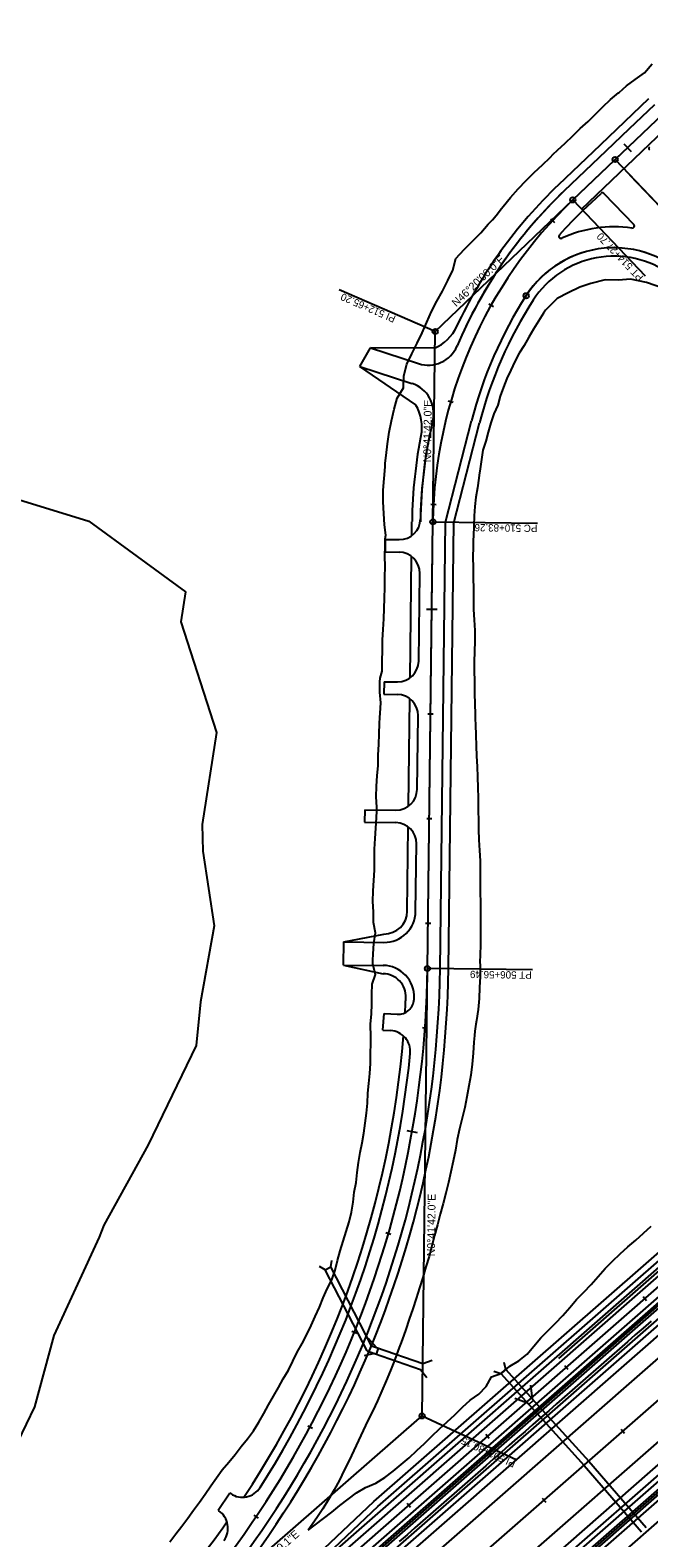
# Model space of a CAD drawing. Extents: x 1300404 to 1323571, y 234004 to 252077.
# Drawn here: x 1309592 to 1310184, y 240349 to 241789 of the extents above; entities that cross this region are included whole.
import ezdxf

# ---------------------------------------------------------------- set-up
doc = ezdxf.new("R2010")
doc.units = 0
for name, color, linetype in [('R_Barrier Wall', 7, 'Continuous'), ('R_Box Culvert', 7, 'Continuous'), ('R_Const Limits', 7, 'Continuous'), ('R_Draft', 7, 'Continuous'), ('R_Exist Box Culvert', 7, 'Continuous'), ('R_Future', 7, 'Continuous'), ('R_Horz Alg Annot', 7, 'Continuous'), ('R_Horz Alg Annot Leader', 7, 'Continuous'), ('R_Horz Alg Major Ticks', 7, 'Continuous'), ('R_Horz Alg Minor Ticks', 7, 'Continuous'), ('R_Horz Alg Tangents', 7, 'Continuous'), ('R_Horz Alg Tangents Text', 7, 'Continuous'), ('R_Lane Edge', 7, 'Continuous'), ('R_Proposed', 7, 'Continuous'), ('R_Shoulder', 7, 'Continuous'), ('T_Drafting', 7, 'Continuous')]:
    doc.layers.add(name, color=color, linetype=linetype)

msp = doc.modelspace()

# ---------------------------------------------------------------- linework, layer by layer
at = {"layer": 'R_Barrier Wall'}
for p, q in [((1309593.6, 240046.8), (1310899.2, 241188.4)), ((1309594.9, 240045.3), (1310900.5, 241186.9))]:
    msp.add_line(p, q, dxfattribs=at)
at = {"layer": 'R_Box Culvert'}
for p, q in [((1309874.4, 240605), (1309869, 240608.2)), ((1309874.4, 240605), (1309879.8, 240607.8)), ((1309914.5, 240527.6), (1309874.4, 240605)), ((1309879.8, 240607.8), (1309880.7, 240614)), ((1309918.7, 240532.5), (1309879.8, 240607.8)), ((1309918.7, 240532.5), (1309923.6, 240530.8)), ((1309923.5, 240524.5), (1309925.5, 240530.2)), ((1309923.6, 240530.8), (1309925.5, 240530.2)), ((1309914.5, 240527.6), (1309921.6, 240525.2)), ((1309921.6, 240525.2), (1309923.5, 240524.5)), ((1310045.5, 240516.9), (1310046.9, 240510.1)), ((1310035.9, 240508.2), (1310042.5, 240506)), ((1310042.5, 240506), (1310046.9, 240510.1)), ((1310042.5, 240506), (1310069.4, 240476.4)), ((1310046.9, 240510.1), (1310073.8, 240480.5)), ((1310069.4, 240476.4), (1310073.8, 240480.5))]:
    msp.add_line(p, q, dxfattribs=at)
at = {"layer": 'R_Const Limits'}
for points in [[(1309726, 240345.2), (1309731.7, 240352.8), (1309737.4, 240360.3), (1309743.1, 240367.8), (1309748.7, 240375.4), (1309754.3, 240383.1), (1309759.7, 240390.8), (1309765.1, 240398.6), (1309770.4, 240406.4), (1309776, 240414), (1309782.2, 240421.3), (1309788.4, 240428.6), (1309794.2, 240436.2), (1309800.2, 240443.7), (1309805.8, 240451.4), (1309810.9, 240459.5), (1309815.7, 240467.7), (1309820.4, 240476), (1309825, 240484.3), (1309829.7, 240492.7), (1309834.4, 240501), (1309839.4, 240509.2), (1309843.4, 240517.8), (1309847.7, 240526.4), (1309852.4, 240534.7), (1309857, 240543.2), (1309861.1, 240551.8), (1309865, 240560.6), (1309868.9, 240569.3), (1309872.5, 240578.2), (1309876.3, 240587), (1309881, 240595.5), (1309883.9, 240604.7), (1309886.2, 240614), (1309888.9, 240623.2), (1309891.7, 240632.4), (1309894.6, 240641.6), (1309897.3, 240650.8), (1309899.5, 240660.1), (1309901.2, 240669.6), (1309902.3, 240679.2), (1309904, 240688.6), (1309905.1, 240698.2), (1309906.4, 240707.6), (1309907.9, 240717.1), (1309909.9, 240726.4), (1309911.5, 240735.8), (1309912.8, 240745.2), (1309914, 240754.7), (1309914.8, 240764.2), (1309915.4, 240773.7), (1309916.3, 240783.2), (1309917.3, 240792.6), (1309917.8, 240802.1), (1309917.9, 240811.6), (1309918, 240821.2), (1309918.1, 240830.7), (1309917.9, 240836.3), (1309917.9, 240840.1), (1309918.5, 240846.3), (1309918.5, 240846.3), (1309918.8, 240849.6), (1309919.1, 240859), (1309919.1, 240868.5), (1309919.3, 240877.9), (1309922.7, 240887.3), (1309919.9, 240897), (1309920, 240900.6), (1309920.3, 240907), (1309920.9, 240917), (1309922.6, 240927), (1309920.6, 240937), (1309920.6, 240947), (1309920.1, 240957), (1309920.4, 240967), (1309921.1, 240977), (1309921.5, 240987), (1309921.7, 240997), (1309921.8, 241007), (1309922.4, 241017), (1309922.9, 241027), (1309923.5, 241037), (1309923.8, 241043.5), (1309923.8, 241047), (1309923.4, 241057), (1309923.5, 241067), (1309924.2, 241077), (1309925.1, 241087), (1309925.1, 241097), (1309925.9, 241107), (1309926.2, 241117), (1309926.5, 241126.9), (1309926.8, 241132.7), (1309927.2, 241136.9), (1309927.7, 241146.9), (1309926.9, 241156.9), (1309926.8, 241166.9), (1309927.2, 241170.2), (1309928.9, 241176.9), (1309929.1, 241186.9), (1309929.4, 241196.9), (1309929.4, 241206.9), (1309930, 241216.9), (1309930.5, 241226.9), (1309930.9, 241236.9), (1309931.2, 241246.9), (1309931.4, 241256.9), (1309931.6, 241266.9), (1309931.9, 241276.9), (1309931.4, 241286.9), (1309931.9, 241296.9), (1309931.9, 241303.5), (1309932.6, 241306.9), (1309931.2, 241316.9), (1309930.6, 241327.6), (1309930.1, 241338.8), (1309930.1, 241349.9), (1309930.8, 241361), (1309931.7, 241372.1), (1309932, 241375.7), (1309932.7, 241383.2), (1309934.1, 241394.3), (1309935.8, 241405.3), (1309937.9, 241416.3), (1309940.5, 241427.2), (1309943.4, 241437.9), (1309949.5, 241447.8), (1309949.8, 241459.3), (1309952.6, 241470.2), (1309957.3, 241480.3), (1309962.3, 241490.3), (1309967.3, 241500.3), (1309971.8, 241510.5), (1309976.2, 241520.7), (1309981.3, 241530.5), (1309986.7, 241540.2), (1309991.8, 241550.1), (1309996.6, 241560.2), (1309999.5, 241571.4), (1310007.3, 241579.7), (1310015.3, 241587.7), (1310023.2, 241595.7), (1310030.4, 241603.9), (1310030.5, 241604), (1310034.4, 241608.3), (1310037.9, 241612.3), (1310043.2, 241618.9), (1310044.7, 241620.9), (1310051.6, 241629.6), (1310058.9, 241637.8), (1310066.6, 241645.8), (1310074.5, 241653.4), (1310082.4, 241660.8), (1310089.5, 241667.8), (1310092.6, 241670.9), (1310096.7, 241674.8), (1310104, 241681.6), (1310111.3, 241688.4), (1310118.5, 241695.4), (1310126, 241702), (1310133, 241709.1), (1310140.1, 241716.2), (1310147.4, 241723), (1310155, 241729.6), (1310155.5, 241730), (1310162.5, 241736.2), (1310170.8, 241742.4), (1310179.9, 241748.7), (1310187.1, 241757.1)], [(1310166.5, 241551.6), (1310154.9, 241550.5), (1310142.4, 241550.8), (1310128.7, 241547.4), (1310118, 241543.8), (1310107, 241538.5), (1310096.2, 241532.9), (1310085.2, 241521.8), (1310083.3, 241518.9), (1310078.4, 241511.5), (1310073.7, 241503.9), (1310069.2, 241496.2), (1310064.9, 241488.3), (1310060.1, 241480.7), (1310055.8, 241472.9), (1310052, 241464.7), (1310048.1, 241456.6), (1310044.9, 241448.2), (1310041.7, 241439.8), (1310039.5, 241431.1), (1310035.8, 241422.8), (1310033, 241414.2), (1310030.5, 241405.5), (1310028, 241396.8), (1310025.2, 241388.2), (1310024.1, 241379.2), (1310022.7, 241370.3), (1310021.8, 241364.2), (1310021.4, 241361.3), (1310020, 241352.3), (1310018.6, 241343.4), (1310017.7, 241334.3), (1310017, 241325.3), (1310016.6, 241315.9), (1310016.2, 241305.9), (1310016.1, 241302.5), (1310015.9, 241295.9), (1310015.8, 241285.9), (1310015.9, 241275.9), (1310016.1, 241265.9), (1310016.4, 241255.9), (1310016.4, 241245.9), (1310016.4, 241235.9), (1310016.9, 241225.9), (1310017.6, 241215.9), (1310017.6, 241205.8), (1310017.3, 241195.9), (1310017.1, 241185.9), (1310017.1, 241175.9), (1310017.2, 241169.1), (1310017.3, 241165.9), (1310017.4, 241155.8), (1310017.6, 241145.8), (1310017.9, 241135.8), (1310017.9, 241131.6), (1310018.1, 241125.8), (1310018.6, 241115.8), (1310019, 241105.8), (1310019.3, 241095.8), (1310019.8, 241085.8), (1310020.2, 241075.8), (1310020.5, 241065.8), (1310020.7, 241055.8), (1310020.8, 241045.8), (1310020.9, 241042.3), (1310021, 241035.8), (1310021.1, 241025.8), (1310021.5, 241015.8), (1310022.2, 241005.8), (1310022.7, 240995.8), (1310022.6, 240985.8), (1310022.7, 240975.8), (1310022.8, 240965.8), (1310022.9, 240955.8), (1310022.9, 240945.8), (1310022.9, 240935.8), (1310022.9, 240925.8), (1310023, 240915.8), (1310022.6, 240905.8), (1310022.5, 240899.4), (1310022.6, 240895.8), (1310022.6, 240885.4), (1310022.2, 240874.9), (1310021.6, 240864.4), (1310020.7, 240853.9), (1310019.3, 240843.4), (1310018.7, 240839.8), (1310018.7, 240839.8), (1310017.7, 240833), (1310017.3, 240828.8), (1310016.7, 240822.6), (1310016.1, 240812.1), (1310015.1, 240801.6), (1310013.7, 240791.2), (1310012, 240780.9), (1310010, 240770.5), (1310007.9, 240760.2), (1310005.5, 240750), (1310002.8, 240739.8), (1310000.8, 240729.6), (1309999.1, 240719.3), (1309996.9, 240709), (1309994.8, 240698.8), (1309992.4, 240688.6), (1309989.9, 240678.4), (1309987.2, 240668.3), (1309984.6, 240658.2), (1309981.8, 240648.2), (1309979.1, 240638), (1309976.5, 240627.9), (1309973.8, 240617.8), (1309970.9, 240607.8), (1309967.9, 240597.7), (1309964.8, 240587.8), (1309961.6, 240577.8), (1309958.3, 240567.9), (1309954.8, 240558), (1309951.5, 240548.1), (1309948, 240538.2), (1309944.4, 240528.4), (1309940.7, 240518.6), (1309936.8, 240508.8), (1309932.8, 240499.1), (1309928.6, 240489.5), (1309924.4, 240479.9), (1309919.9, 240470.4), (1309915.4, 240461), (1309910.9, 240451.5), (1309906.5, 240442), (1309902, 240432.5), (1309897.4, 240423), (1309892.8, 240413.6), (1309888.1, 240404.2), (1309883.1, 240394.9), (1309877.8, 240385.8), (1309872.2, 240376.9), (1309866.5, 240368), (1309860.5, 240359.4), (1309858.3, 240356.4)], [(1310197.3, 241542.9), (1310181.8, 241548.3), (1310166.5, 241551.6)], [(1309568.6, 241344.9), (1309648.3, 241320.2), (1309740.8, 241252.9), (1309738.6, 241238.5), (1309736.3, 241224.2), (1309770.5, 241118.4), (1309756.9, 241030.5), (1309757.2, 241017.8), (1309757.5, 241005.1), (1309768.3, 240933.7), (1309755.1, 240861.2), (1309751.1, 240819.5), (1309705.1, 240724.5), (1309662.8, 240647.6), (1309658.4, 240636.3), (1309615.1, 240542.2), (1309596.6, 240474.1), (1309564.7, 240408)], [(1309858.3, 240356.4), (1309864.9, 240361.4), (1309872.8, 240367.5), (1309880.7, 240373.7), (1309888.6, 240379.8), (1309896.5, 240386), (1309904.4, 240392.1), (1309913.2, 240397.2), (1309922.8, 240401.4), (1309931.5, 240406.6), (1309939.6, 240412.6), (1309947.3, 240419), (1309954.9, 240425.5), (1309962.2, 240432.4), (1309969.4, 240439.3), (1309976.6, 240446.3), (1309983.9, 240453.2), (1309991.2, 240459.9), (1309998.6, 240466.7), (1310005.7, 240473.8), (1310013, 240480.6), (1310021.3, 240486.4), (1310028.3, 240493.5), (1310033.5, 240502.7), (1310043.5, 240506.4), (1310051.2, 240512.9), (1310059.8, 240518.2), (1310067.5, 240524.6), (1310074, 240532.3), (1310080.6, 240540), (1310087.7, 240547.1), (1310094.8, 240554.2), (1310101.8, 240561.3), (1310108.4, 240569), (1310114.9, 240576.7), (1310121.9, 240583.9), (1310128.8, 240591.2), (1310135.5, 240598.7), (1310142.3, 240606.2), (1310149.3, 240613.4), (1310156.5, 240620.3), (1310164, 240626.9), (1310171.6, 240633.4), (1310179, 240640.1), (1310186.4, 240646.9)], [(1310186.1, 240556.1), (1310178.6, 240549.5), (1310171.1, 240542.9), (1310163.5, 240536.3), (1310156, 240529.7), (1310148.5, 240523.2), (1310141, 240516.6), (1310133.4, 240510), (1310125.9, 240503.4), (1310118.4, 240496.8), (1310110.8, 240490.2), (1310103.3, 240483.7), (1310095.8, 240477.1), (1310088.3, 240470.5), (1310080.7, 240463.9), (1310073.2, 240457.3), (1310065.7, 240450.7), (1310058.1, 240444.2), (1310050.6, 240437.6), (1310043.1, 240431), (1310035.6, 240424.4), (1310028, 240417.8), (1310020.5, 240411.2), (1310013, 240404.7), (1310005.4, 240398.1), (1309997.9, 240391.5), (1309990.4, 240384.9), (1309982.9, 240378.3), (1309975.3, 240371.8), (1309967.8, 240365.2), (1309960.3, 240358.6), (1309952.8, 240352), (1309945.2, 240345.4)]]:
    msp.add_lwpolyline(points, dxfattribs=at)
at = {"layer": 'R_Draft'}
for p, q in [((1308397, 238971.9), (1312368.4, 242444.5)), ((1308407.8, 238959.5), (1312379.2, 242432.1)), ((1308447.3, 238914.3), (1312418.7, 242386.9)), ((1308458.2, 238901.9), (1312429.6, 242374.5)), ((1309037.8, 239548.2), (1312137.6, 242258.7)), ((1309184.5, 239689.1), (1312131.4, 242265.9)), ((1309193.7, 239678.5), (1312140.6, 242255.3)), ((1309413.9, 239721.6), (1312065.7, 242040.4)), ((1309410.9, 239725), (1311988, 241978.4)), ((1309410.9, 239725), (1311988, 241978.4)), ((1310119.6, 241618.5), (1310206.2, 241701.1)), ((1309989.5, 241319.5), (1310014.4, 241416.3))]:
    msp.add_line(p, q, dxfattribs=at)
for centre, radius, start, end in [((1310150.7, 241481.5), 100, 43.6667, 147.1004), ((1310409.9, 241314.4), 408.4, 147.1626, 165.5481)]:
    msp.add_arc(centre, radius, start, end, dxfattribs=at)
at = {"layer": 'R_Exist Box Culvert'}
for p, q in [((1309923.6, 240530.8), (1309915.8, 240539.4)), ((1309923.6, 240530.8), (1309967.8, 240515.6)), ((1309921.6, 240525.2), (1309911.7, 240523)), ((1309921.6, 240525.2), (1309965.8, 240510)), ((1309967.8, 240515.6), (1309976.8, 240518.7)), ((1309965.8, 240510), (1309971.6, 240502.3)), ((1310070.8, 240494.8), (1310072.5, 240481.9)), ((1310055.9, 240482.4), (1310068, 240477.9)), ((1310068, 240477.9), (1310122.2, 240418.3)), ((1310072.5, 240481.9), (1310126.6, 240422.4)), ((1310122.2, 240418.3), (1310176.9, 240354.8)), ((1310126.6, 240422.4), (1310181.4, 240358.8))]:
    msp.add_line(p, q, dxfattribs=at)
at = {"layer": 'R_Future'}
for p, q in [((1311714.8, 241726.2), (1309950.4, 240183.5)), ((1311716.1, 241724.7), (1309951.7, 240182)), ((1311717.4, 241723.2), (1309953.1, 240180.5)), ((1311720, 241720.2), (1309955.7, 240177.5)), ((1310616.7, 240735.5), (1309965.6, 240166.2)), ((1309921, 240383.6), (1310222.1, 240646.9)), ((1309924.9, 240379), (1310226, 240642.3)), ((1310097.8, 240520.3), (1310231, 240636.7)), ((1309920.8, 240383.4), (1309702.3, 240177.7)), ((1309924.9, 240379), (1309706.3, 240173.3))]:
    msp.add_line(p, q, dxfattribs=at)
at = {"layer": 'R_Horz Alg Annot Leader'}
for points in [[(1310111.3, 241627.2), (1310180.4, 241554.8)], [(1309979.7, 241501.5), (1309888, 241541.4)], [(1309977.5, 241319.6), (1310077.5, 241318.4)], [(1310072.7, 240891.6), (1309972.3, 240892.9)], [(1309967.2, 240465.5), (1310057.9, 240423.5)]]:
    msp.add_lwpolyline(points, dxfattribs=at)
at = {"layer": 'R_Horz Alg Major Ticks'}
for points in [[(1310155.4, 241669.2), (1310148.2, 241662.3)], [(1310160.2, 241680.7), (1310167.1, 241673.5)], [(1309971.5, 241236.4), (1309981.5, 241236.3)], [(1309952.7, 240738.1), (1309962.6, 240736.4)]]:
    msp.add_lwpolyline(points, dxfattribs=at)
at = {"layer": 'R_Horz Alg Minor Ticks'}
for points in [[(1310090.1, 241609.1), (1310093.8, 241605.7)], [(1310031, 241527.9), (1310035.4, 241525.5)], [(1309992.2, 241435.4), (1309997, 241434)], [(1309975.5, 241336.5), (1309980.5, 241336.2)], [(1309972.8, 241136.4), (1309977.8, 241136.3)], [(1309971.6, 241036.4), (1309976.6, 241036.3)], [(1309970.4, 240936.4), (1309975.4, 240936.3)], [(1309967.5, 240836.6), (1309972.5, 240836.3)], [(1309932.6, 240640.6), (1309937.4, 240639.2)], [(1310178.6, 240579.6), (1310181.9, 240575.9)], [(1309900, 240546.4), (1309904.7, 240544.5)], [(1310103.4, 240513.8), (1310106.7, 240510.1)], [(1309857.8, 240456.1), (1309862.2, 240453.7)], [(1310028.1, 240448), (1310031.4, 240444.2)], [(1310157.4, 240452.8), (1310160.7, 240449)], [(1310082.1, 240386.9), (1310085.4, 240383.2)], [(1309806.3, 240370.7), (1309810.4, 240367.9)], [(1309952.8, 240382.2), (1309956.1, 240378.4)]]:
    msp.add_lwpolyline(points, dxfattribs=at)
at = {"layer": 'R_Horz Alg Tangents'}
for p, q in [((1309979.7, 241501.5), (1310111.3, 241627.2)), ((1309977.5, 241319.6), (1309979.7, 241501.5)), ((1309967.2, 240465.5), (1309972.3, 240892.9)), ((1309645, 240184.6), (1309967.2, 240465.5))]:
    msp.add_line(p, q, dxfattribs=at)
at = {"layer": 'R_Lane Edge'}
for p, q in [((1310165.2, 241695.2), (1310189.6, 241718.4)), ((1310143.5, 241674.4), (1310165.2, 241695.2)), ((1310103.1, 241635.8), (1310143.5, 241674.4)), ((1310121, 241617), (1310138.3, 241633.5)), ((1310141.1, 241633.5), (1310169.6, 241603.6)), ((1309907.7, 241468.2), (1309917.8, 241486)), ((1309917.8, 241486), (1309963.7, 241470.9)), ((1309907.7, 241468.2), (1309957.5, 241451.9)), ((1309989.5, 241319.5), (1310014.4, 241416.3)), ((1309984.3, 240892.7), (1309989.5, 241319.5)), ((1309932, 241302.9), (1309931.9, 241290.9)), ((1309932, 241302.9), (1309945.3, 241302.7)), ((1309931.9, 241290.9), (1309945.2, 241290.7)), ((1309963.9, 241186.5), (1309964.9, 241270.5)), ((1309579.8, 240062.7), (1310885.3, 241204.2)), ((1309589.7, 240051.4), (1310895.2, 241193)), ((1309930.9, 241166.9), (1309930.7, 241154.9)), ((1309930.9, 241166.9), (1309943.7, 241166.8)), ((1309930.7, 241154.9), (1309943.5, 241154.8)), ((1309962.4, 241064), (1309963.3, 241134.5)), ((1309912.3, 241044.6), (1309912.2, 241032.6)), ((1309912.3, 241044.6), (1309942.2, 241044.3)), ((1309912.2, 241032.6), (1309942, 241032.3)), ((1309961, 240947.5), (1309961.8, 241012)), ((1309892.1, 240896.3), (1309892.4, 240918.3)), ((1309892.4, 240918.3), (1309930.6, 240917.9)), ((1309892.1, 240896.3), (1309930, 240895.9)), ((1309929.7, 240834.2), (1309930.8, 240850.1)), ((1309930.8, 240850.1), (1309943.5, 240849.3)), ((1309929.7, 240834.2), (1309937.3, 240833.7)), ((1309772, 240375.4), (1309783.3, 240391.9)), ((1309783.3, 240391.9), (1309784.1, 240391.3)), ((1309772, 240375.4), (1309772.8, 240374.8))]:
    msp.add_line(p, q, dxfattribs=at)
for centre, radius, start, end in [((1310186, 241676.3), 2, 133.6667, 223.6667), ((1310409.9, 241314.4), 444.4, 133.6667, 157.0383), ((1310409.9, 241314.4), 444.4, 133.6667, 154.9082), ((1310139.7, 241632.1), 2, 43.6667, 133.6667), ((1310409.9, 241314.4), 418.4, 133.6667, 138.1011), ((1310150.7, 241481.5), 120, 81.7713, 114.5833), ((1310168.2, 241602.3), 2, 261.7713, 43.6667), ((1310150.7, 241481.5), 100, 43.6667, 147.1828), ((1310100, 241592.5), 2, 138.1011, 294.5833), ((1310409.9, 241314.4), 408.4, 147.1626, 165.5481), ((1309973.1, 241499.4), 30, 251.8748, 337.0383), ((1309948.2, 241423.4), 30, 346.7116, 71.8748), ((1310409.9, 241314.4), 444.4, 166.7113, 179.305), ((1310409.9, 241314.4), 444.4, 168.3528, 179.305), ((1309945.6, 241322.7), 20, 269.305, 359.305), ((1309944.9, 241270.7), 20, 359.305, 89.305), ((1309943.9, 241186.8), 20, 269.305, 359.305), ((1309943.3, 241134.8), 20, 359.305, 89.305), ((1309942.4, 241064.3), 20, 269.305, 359.305), ((1309941.8, 241012.3), 20, 359.305, 89.305), ((1309931, 240947.9), 30, 269.305, 359.305), ((1309017.5, 240904.4), 966.9, 311.0808, 359.305), ((1309929.6, 240865.9), 30, 357.5799, 89.305), ((1309944.5, 240864.2), 15, 266.096, 357.5163), ((1309017.5, 240904.4), 942.9, 357.5163, 357.5799), ((1309935.9, 240813.7), 20, 354.3575, 86.096), ((1309017.5, 240904.4), 942.9, 327.4472, 354.3575), ((1309795.4, 240407.8), 20, 235.5845, 327.4472), ((1309761.5, 240358.3), 20, 323.7218, 55.5845)]:
    msp.add_arc(centre, radius, start, end, dxfattribs=at)
at = {"layer": 'R_Proposed'}
for p, q in [((1308463.1, 238968), (1312793.8, 242754.8)), ((1308427.6, 238936.9), (1312399, 242409.5)), ((1309180.4, 239595.2), (1312399, 242409.5)), ((1309180.4, 239595.2), (1312399, 242409.5)), ((1309180.4, 239595.2), (1312051.5, 242105.7)), ((1310111.3, 241627.2), (1310197.9, 241709.8)), ((1310111.3, 241627.2), (1310197.9, 241709.8)), ((1310111.3, 241627.2), (1310197.9, 241709.8)), ((1310151.8, 241665.8), (1310197.9, 241709.8)), ((1310111.3, 241627.2), (1310151.8, 241665.8)), ((1310151.8, 241665.8), (1311952.6, 239779.2)), ((1310165.6, 241651.3), (1311952.6, 239779.1)), ((1310165.6, 241651.3), (1311952.6, 239779.1)), ((1309977.4, 241402.4), (1309977.4, 241402.4)), ((1309972.3, 240892.9), (1309977.5, 241319.6)), ((1309972.3, 240892.9), (1309977.5, 241319.6)), ((1309972.3, 240892.9), (1309977.2, 241291.6)), ((1309972.3, 240892.9), (1309977.2, 241291.6)), ((1309972.3, 240892.9), (1309977.2, 241291.6)), ((1309584.7, 240057), (1310889.7, 241198))]:
    msp.add_line(p, q, dxfattribs=at)
for centre in [(1310151.8, 241665.8), (1310111.3, 241627.2), (1310066.7, 241535.7), (1309979.7, 241501.5), (1309977.5, 241319.6), (1309972.3, 240892.9), (1309967.2, 240465.5)]:
    msp.add_circle(centre, 2.5, dxfattribs=at)
for centre, radius, start, end in [((1310409.9, 241314.4), 432.4, 133.6667, 179.305), ((1310150.7, 241481.5), 100, 43.6667, 147.1828), ((1309017.5, 240904.4), 954.9, 311.0808, 359.305), ((1309017.5, 240904.4), 954.9, 311.0808, 359.305)]:
    msp.add_arc(centre, radius, start, end, dxfattribs=at)
at = {"layer": 'R_Shoulder'}
for p, q in [((1310138, 241680.2), (1310184.1, 241724.2)), ((1310097.5, 241641.6), (1310138, 241680.2)), ((1309978.9, 241485.6), (1309917.8, 241486)), ((1309961.2, 241431.3), (1309907.7, 241468.2)), ((1309997.3, 241317.5), (1310022.2, 241414.3)), ((1309957.4, 241306.6), (1309957.5, 241319.8)), ((1309992.3, 240892.6), (1309997.5, 241319.4)), ((1309955.7, 241170.6), (1309957.1, 241286.6)), ((1309575.8, 240067.2), (1310881.4, 241208.7)), ((1309592.3, 240048.3), (1310897.9, 241189.9)), ((1309954.2, 241048.1), (1309955.5, 241150.6)), ((1309953, 240947.6), (1309954, 241028.1)), ((1309892.4, 240918.3), (1309930.7, 240925.9)), ((1309892.1, 240896.3), (1309929.9, 240887.9))]:
    msp.add_line(p, q, dxfattribs=at)
for centre, radius, start, end in [((1310409.9, 241314.4), 452.4, 133.6667, 154.9074), ((1310150.7, 241481.5), 92, 54.0272, 147.1828), ((1310409.9, 241314.4), 400.4, 147.1633, 165.5481), ((1309962.2, 241524.1), 42, 293.4618, 334.9767), ((1309925, 241410), 42, 348.9172, 30.4321), ((1310409.9, 241314.4), 452.4, 168.3977, 179.305), ((1309931, 240947.9), 22, 269.305, 359.305), ((1309017.5, 240904.4), 974.9, 311.0808, 359.305), ((1309929.6, 240865.9), 22, 357.5799, 89.305), ((1309017.5, 240904.4), 934.9, 356.7002, 357.5799), ((1309017.5, 240904.4), 934.9, 326.4603, 355.3444), ((1309017.5, 240904.4), 934.9, 317.7944, 324.7087)]:
    msp.add_arc(centre, radius, start, end, dxfattribs=at)
at = {"layer": 'T_Drafting'}
msp.add_arc((1310409.9, 241314.4), 432.4, 133.6667, 179.305, dxfattribs=at)

# ---------------------------------------------------------------- texts
at = {"layer": 'R_Horz Alg Annot'}
for s, rotation, p in [('PT 514+27.70', 133.6667, (1310179.3, 241553.8)), ('PI 512+65.20', 156.4858, (1309942.6, 241516.1)), ('PC 510+83.26', 179.305, (1310077.5, 241316.9)), ('PT 506+56.49', 179.305, (1310072.1, 240890.1)), ('PI 502+80.15', 155.1929, (1310057.3, 240422.2))]:
    msp.add_text(s, height=7, rotation=rotation, dxfattribs=at).set_placement(p)
at = {"layer": 'R_Horz Alg Tangents Text'}
for s, rotation, p in [('N46%%d20\'00.0"E', 43.6667, (1309999.8, 241524.7)), ('N0%%d41\'42.0"E', 89.305, (1309975.7, 241376.5)), ('N0%%d41\'42.0"E', 89.305, (1309979.4, 240618)), ('N48%%d55\'09.1"E', 41.0808, (1309801.2, 240308.5))]:
    msp.add_text(s, height=7.5, rotation=rotation, dxfattribs=at).set_placement(p)

doc.saveas('drawing.dxf')
